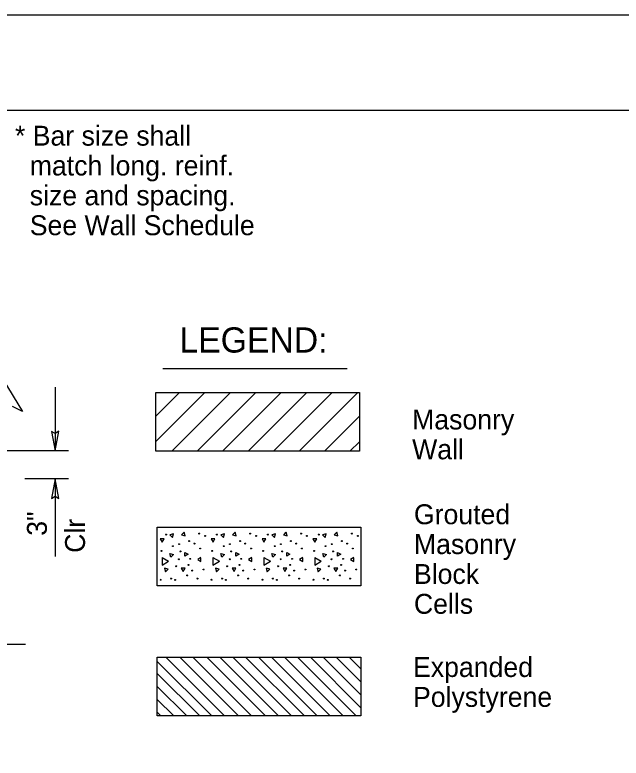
# Model space of a CAD drawing. Extents: x 0 to 2.83, y -0.03 to 1.83.
# Drawn here: x 0.6752 to 1.0716, y 1.3472 to 1.8333 of the extents above; entities that cross this region are included whole.
import ezdxf

# ---------------------------------------------------------------- set-up
doc = ezdxf.new("R2010")
doc.units = 0
for name, color, linetype in [('50', 7, 'Continuous'), ('51', 7, 'Continuous'), ('52', 7, 'Continuous'), ('54', 7, 'Continuous'), ('55', 7, 'Continuous'), ('57', 7, 'Continuous'), ('63', 7, 'Continuous')]:
    doc.layers.add(name, color=color, linetype=linetype)

msp = doc.modelspace()

# ---------------------------------------------------------------- linework, layer by layer
at = {"layer": '50'}
for p, q in [((0.78273, 1.58632), (0.76733, 1.57092)), ((0.79939, 1.58632), (0.76733, 1.55425)), ((0.81605, 1.58632), (0.77769, 1.54794)), ((0.83267, 1.58632), (0.79427, 1.54794)), ((0.84933, 1.58632), (0.81095, 1.54794)), ((0.866, 1.58632), (0.82762, 1.54794)), ((0.88267, 1.58632), (0.84429, 1.54794)), ((0.89933, 1.58632), (0.86095, 1.54794)), ((0.90047, 1.57079), (0.87762, 1.54794)), ((0.90047, 1.55413), (0.89428, 1.54794)), ((0.76828, 1.41041), (0.80387, 1.37482)), ((0.77395, 1.4132), (0.81233, 1.37482)), ((0.78302, 1.4132), (0.8214, 1.37482)), ((0.79148, 1.4132), (0.82987, 1.37482)), ((0.80065, 1.4132), (0.83904, 1.37482)), ((0.80912, 1.4132), (0.8475, 1.37482)), ((0.81758, 1.4132), (0.85596, 1.37482)), ((0.82604, 1.4132), (0.86443, 1.37482)), ((0.83451, 1.4132), (0.87289, 1.37482)), ((0.84297, 1.4132), (0.88135, 1.37482)), ((0.85144, 1.4132), (0.88982, 1.37482)), ((0.8599, 1.4132), (0.89828, 1.37482)), ((0.86836, 1.4132), (0.90141, 1.38015)), ((0.87683, 1.4132), (0.90141, 1.38861)), ((0.88529, 1.4132), (0.90141, 1.39707)), ((0.89375, 1.4132), (0.90141, 1.40554)), ((0.76828, 1.40255), (0.79601, 1.37482)), ((0.76828, 1.39408), (0.78755, 1.37482)), ((0.76828, 1.38562), (0.77908, 1.37482)), ((0.76828, 1.37716), (0.77062, 1.37482))]:
    msp.add_line(p, q, dxfattribs=at)
for centre in [(0.77402, 1.49336), (0.79573, 1.49402), (0.79956, 1.49253), (0.8073, 1.49336), (0.82901, 1.49402), (0.83284, 1.49253), (0.84058, 1.49336), (0.86229, 1.49402), (0.86613, 1.49253), (0.87387, 1.49336), (0.89558, 1.49402), (0.89941, 1.49253), (0.78913, 1.48913), (0.79256, 1.48755), (0.82241, 1.48913), (0.82584, 1.48755), (0.85569, 1.48913), (0.85913, 1.48755), (0.88898, 1.48913), (0.89241, 1.48755), (0.77093, 1.48275), (0.77847, 1.48583), (0.78248, 1.48715), (0.7834, 1.48244), (0.7963, 1.48429), (0.80422, 1.48275), (0.81175, 1.48583), (0.81576, 1.48715), (0.81668, 1.48244), (0.82958, 1.48429), (0.8375, 1.48275), (0.84503, 1.48583), (0.84904, 1.48715), (0.84997, 1.48244), (0.86287, 1.48429), (0.87078, 1.48275), (0.87832, 1.48583), (0.88233, 1.48715), (0.88325, 1.48244), (0.89615, 1.48429), (0.78067, 1.47271), (0.78238, 1.47724), (0.78864, 1.47354), (0.78988, 1.47755), (0.81395, 1.47271), (0.81567, 1.47724), (0.82193, 1.47354), (0.82316, 1.47755), (0.84723, 1.47271), (0.84895, 1.47724), (0.85521, 1.47354), (0.85644, 1.47755), (0.88052, 1.47271), (0.88223, 1.47724), (0.88849, 1.47354), (0.88973, 1.47755), (0.79119, 1.46989), (0.79855, 1.47059), (0.82448, 1.46989), (0.83183, 1.47059), (0.85776, 1.46989), (0.86512, 1.47059), (0.89104, 1.46989), (0.8984, 1.47059), (0.77049, 1.4639), (0.77733, 1.4646), (0.77988, 1.46377), (0.78784, 1.46672), (0.79449, 1.4646), (0.80378, 1.4639), (0.81061, 1.4646), (0.81316, 1.46377), (0.82113, 1.46672), (0.82778, 1.4646), (0.83706, 1.4639), (0.84389, 1.4646), (0.84644, 1.46377), (0.85441, 1.46672), (0.86106, 1.4646), (0.87034, 1.4639), (0.87718, 1.4646), (0.87973, 1.46377), (0.88769, 1.46672), (0.89434, 1.4646)]:
    msp.add_circle(centre, 0.000305, dxfattribs=at)
at = {"layer": '51'}
for p, q in [((0.77137, 1.47847), (0.77137, 1.47351)), ((0.77137, 1.47846), (0.77567, 1.476)), ((0.80465, 1.47847), (0.80465, 1.47351)), ((0.80465, 1.47846), (0.80895, 1.476)), ((0.83793, 1.47847), (0.83793, 1.47351)), ((0.83793, 1.47846), (0.84223, 1.476)), ((0.87122, 1.47847), (0.87122, 1.47351)), ((0.87122, 1.47846), (0.87552, 1.476)), ((0.77137, 1.47351), (0.77567, 1.47598)), ((0.80465, 1.47351), (0.80895, 1.47598)), ((0.83793, 1.47351), (0.84223, 1.47598)), ((0.87122, 1.47351), (0.87552, 1.47598))]:
    msp.add_line(p, q, dxfattribs=at)
at = {"layer": '52'}
for p, q in [((0.77893, 1.4938), (0.77653, 1.49314)), ((0.77653, 1.49315), (0.77828, 1.49139)), ((0.77828, 1.49139), (0.77893, 1.49379)), ((0.78413, 1.49316), (0.78653, 1.49251)), ((0.78587, 1.49492), (0.78415, 1.49316)), ((0.78653, 1.49251), (0.78588, 1.49491)), ((0.81222, 1.4938), (0.80982, 1.49314)), ((0.80982, 1.49315), (0.81157, 1.49139)), ((0.81157, 1.49139), (0.81222, 1.49379)), ((0.81742, 1.49316), (0.81982, 1.49251)), ((0.81915, 1.49492), (0.81743, 1.49316)), ((0.81982, 1.49251), (0.81917, 1.49491)), ((0.8455, 1.4938), (0.8431, 1.49314)), ((0.8431, 1.49315), (0.84485, 1.49139)), ((0.84485, 1.49139), (0.8455, 1.49379)), ((0.8507, 1.49316), (0.8531, 1.49251)), ((0.85243, 1.49492), (0.85072, 1.49316)), ((0.8531, 1.49251), (0.85245, 1.49491)), ((0.87878, 1.4938), (0.87638, 1.49314)), ((0.87638, 1.49315), (0.87813, 1.49139)), ((0.87813, 1.49139), (0.87878, 1.49379)), ((0.88398, 1.49316), (0.88638, 1.49251)), ((0.88572, 1.49492), (0.884, 1.49316)), ((0.88638, 1.49251), (0.88573, 1.49491)), ((0.77268, 1.49066), (0.77022, 1.49064)), ((0.77022, 1.49065), (0.77145, 1.4885)), ((0.77145, 1.4885), (0.7727, 1.49065)), ((0.80597, 1.49066), (0.8035, 1.49064)), ((0.8035, 1.49065), (0.80473, 1.4885)), ((0.80473, 1.4885), (0.80598, 1.49065)), ((0.83925, 1.49066), (0.83678, 1.49064)), ((0.83678, 1.49065), (0.83802, 1.4885)), ((0.83802, 1.4885), (0.83927, 1.49065)), ((0.87253, 1.49066), (0.87007, 1.49064)), ((0.87007, 1.49065), (0.8713, 1.4885)), ((0.8713, 1.4885), (0.87255, 1.49065)), ((0.77722, 1.47858), (0.77657, 1.48097)), ((0.77658, 1.48097), (0.77897, 1.48034)), ((0.77897, 1.48033), (0.77722, 1.47858)), ((0.78633, 1.47931), (0.78633, 1.48179)), ((0.78633, 1.48178), (0.78848, 1.48056)), ((0.78848, 1.48055), (0.78633, 1.47931)), ((0.79683, 1.47831), (0.79472, 1.47706)), ((0.79685, 1.47582), (0.79685, 1.4783)), ((0.8105, 1.47858), (0.80985, 1.48097)), ((0.80987, 1.48097), (0.81225, 1.48034)), ((0.81225, 1.48033), (0.8105, 1.47858)), ((0.81962, 1.47931), (0.81962, 1.48179)), ((0.81962, 1.48178), (0.82177, 1.48056)), ((0.82177, 1.48055), (0.81962, 1.47931)), ((0.83012, 1.47831), (0.828, 1.47706)), ((0.83013, 1.47582), (0.83013, 1.4783)), ((0.84378, 1.47858), (0.84313, 1.48097)), ((0.84315, 1.48097), (0.84553, 1.48034)), ((0.84553, 1.48033), (0.84378, 1.47858)), ((0.8529, 1.47931), (0.8529, 1.48179)), ((0.8529, 1.48178), (0.85505, 1.48056)), ((0.85505, 1.48055), (0.8529, 1.47931)), ((0.8634, 1.47831), (0.86128, 1.47706)), ((0.86342, 1.47582), (0.86342, 1.4783)), ((0.87707, 1.47858), (0.87642, 1.48097)), ((0.87643, 1.48097), (0.87882, 1.48034)), ((0.87882, 1.48033), (0.87707, 1.47858)), ((0.88618, 1.47931), (0.88618, 1.48179)), ((0.88618, 1.48178), (0.88833, 1.48056)), ((0.88833, 1.48055), (0.88618, 1.47931)), ((0.89668, 1.47831), (0.89457, 1.47706)), ((0.8967, 1.47582), (0.8967, 1.4783)), ((0.7947, 1.47707), (0.79685, 1.47582)), ((0.82798, 1.47707), (0.83013, 1.47582)), ((0.86127, 1.47707), (0.86342, 1.47582)), ((0.89455, 1.47707), (0.8967, 1.47582)), ((0.773, 1.47149), (0.77365, 1.46909)), ((0.7754, 1.47086), (0.77302, 1.47148)), ((0.77365, 1.46909), (0.7754, 1.47085)), ((0.78642, 1.47147), (0.78393, 1.47145)), ((0.78393, 1.47146), (0.78518, 1.46931)), ((0.78518, 1.46931), (0.78642, 1.47146)), ((0.80628, 1.47149), (0.80693, 1.46909)), ((0.80868, 1.47086), (0.8063, 1.47148)), ((0.80693, 1.46909), (0.80868, 1.47085)), ((0.8197, 1.47147), (0.81722, 1.47145)), ((0.81722, 1.47146), (0.81847, 1.46931)), ((0.81847, 1.46931), (0.8197, 1.47146)), ((0.83957, 1.47149), (0.84022, 1.46909)), ((0.84197, 1.47086), (0.83958, 1.47148)), ((0.84022, 1.46909), (0.84197, 1.47085)), ((0.85298, 1.47147), (0.8505, 1.47145)), ((0.8505, 1.47146), (0.85175, 1.46931)), ((0.85175, 1.46931), (0.85298, 1.47146)), ((0.87285, 1.47149), (0.8735, 1.46909)), ((0.87525, 1.47086), (0.87287, 1.47148)), ((0.8735, 1.46909), (0.87525, 1.47085)), ((0.88627, 1.47147), (0.88378, 1.47145)), ((0.88378, 1.47146), (0.88503, 1.46931)), ((0.88503, 1.46931), (0.88627, 1.47146))]:
    msp.add_line(p, q, dxfattribs=at)
at = {"layer": '54'}
for points in [[(0.70148, 1.54809), (0.70385, 1.56108), (0.70148, 1.55957), (0.69908, 1.56093)], [(0.70148, 1.52991), (0.6991, 1.51692), (0.70148, 1.51843), (0.70388, 1.51707)]]:
    msp.add_lwpolyline(points, close=True, dxfattribs=at)
at = {"layer": '55'}
for p, q in [((0.89247, 1.60179), (0.77201, 1.60179)), ((0.6672, 1.595), (0.68022, 1.574)), ((0.70148, 1.58975), (0.70148, 1.54809)), ((0.68022, 1.574), (0.67371, 1.57727)), ((0.71028, 1.54809), (0.65331, 1.54809)), ((0.71028, 1.52991), (0.68161, 1.52991)), ((0.70148, 1.52991), (0.70148, 1.47907)), ((0.50114, 1.42173), (0.68222, 1.42173))]:
    msp.add_line(p, q, dxfattribs=at)
for points in [[(0.76733, 1.58632), (0.90047, 1.58632), (0.90047, 1.54794), (0.76733, 1.54794)], [(0.76828, 1.49835), (0.90141, 1.49835), (0.90141, 1.45997), (0.76828, 1.45997)], [(0.76828, 1.4132), (0.90141, 1.4132), (0.90141, 1.37482), (0.76828, 1.37482)]]:
    msp.add_lwpolyline(points, close=True, dxfattribs=at)
at = {"layer": '63'}
msp.add_line((0, 1.83333), (2.83333, 1.83333), dxfattribs=at)
msp.add_lwpolyline([(2.72918, 1.77077), (0.10418, 1.77077), (0.10418, 0.06244), (2.72918, 0.06244)], close=True, dxfattribs=at)

# ---------------------------------------------------------------- texts
at = {"layer": '55'}
for s, height, p in [('Masonry ', 0.013021, (0.9349, 1.56218)), ('Wall', 0.013021, (0.9349, 1.54265)), ('Grouted ', 0.013021, (0.93609, 1.50019)), ('Masonry ', 0.013021, (0.93609, 1.48066)), ('Block ', 0.013021, (0.93609, 1.46113)), ('Cells', 0.013021, (0.93609, 1.4416)), ('Expanded ', 0.013021, (0.93549, 1.40026)), ('Polystyrene', 0.0130208, (0.93549, 1.38073))]:
    msp.add_text(s, height=height, dxfattribs=at).set_placement(p)
at = {"layer": '57'}
for s, height, p in [('* Bar size shall ', 0.0130167, (0.67524, 1.7478)), ('  match long. reinf. ', 0.0130167, (0.67524, 1.72827)), ('  size and spacing. ', 0.0130167, (0.67524, 1.70875)), ('  See Wall Schedule', 0.0130167, (0.67524, 1.68922)), ('LEGEND:', 0.0165, (0.78274, 1.61245))]:
    msp.add_text(s, height=height, dxfattribs=at).set_placement(p)
for s, p in [('3"', (0.69609, 1.49263)), ('Clr', (0.72101, 1.48147))]:
    msp.add_text(s, height=0.013025, rotation=90, dxfattribs=at).set_placement(p)

doc.saveas('drawing.dxf')
